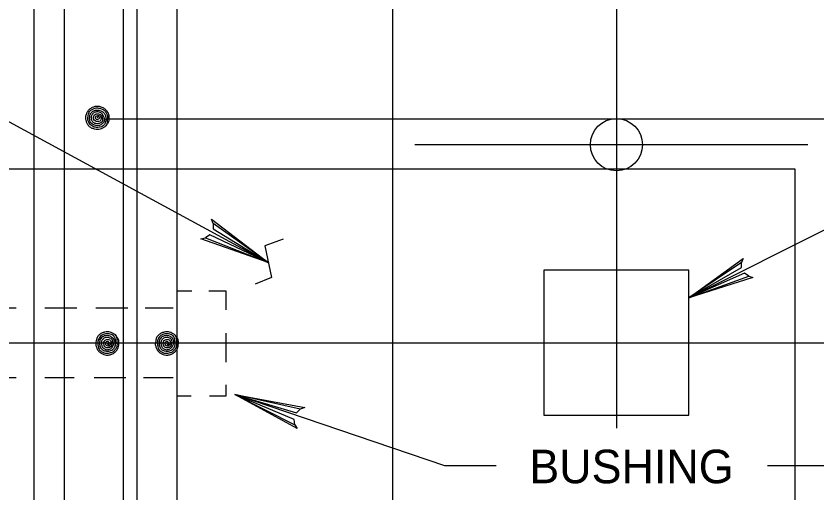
# Model space of a CAD drawing. Extents: x 638455 to 640199, y 298558 to 299152.
# Drawn here: x 638610.5 to 638690.8, y 298970 to 299017.7 of the extents above; entities that cross this region are included whole.
import ezdxf

# ---------------------------------------------------------------- set-up
doc = ezdxf.new("R2010")
doc.units = 0
for name, color, linetype in [('1', 7, 'Continuous'), ('2', 7, 'Continuous'), ('3', 7, 'Continuous')]:
    doc.layers.add(name, color=color, linetype=linetype)

msp = doc.modelspace()

# ---------------------------------------------------------------- linework, layer by layer
at = {"layer": '1'}
msp.add_line((638677.909, 298989.513), (638734.068, 299017.707), dxfattribs=at)
for points in [[(638630.234, 298996.977), (638630.224, 298996.432), (638635.736, 298993.066), (638630.234, 298996.977), (638630.071, 298997.399), (638635.736, 298993.066), (638629.909, 298995.835), (638629.475, 298995.524), (638635.736, 298993.066), (638629.004, 298995.413), (638629.475, 298995.524)], [(638637.232, 298995.376), (638635.411, 298994.726), (638636.062, 298991.537), (638634.436, 298990.886)], [(638638.428, 298976.809), (638638.353, 298977.349), (638632.389, 298979.827), (638638.428, 298976.809), (638638.654, 298976.418), (638632.389, 298979.827), (638638.573, 298977.988), (638638.954, 298978.362), (638632.389, 298979.827), (638639.403, 298978.544), (638638.954, 298978.362)]]:
    msp.add_lwpolyline(points, dxfattribs=at)
at = {"layer": '2'}
for p, q in [((638670.649, 299048.639), (638670.649, 298976.455)), ((638612.27, 298943.574), (638612.27, 299043.396)), ((638615.328, 298928.815), (638615.328, 299041.293)), ((638648.201, 299038.114), (638648.201, 298931.255)), ((638604.496, 299009.982), (638635.736, 298993.066)), ((638619.544, 299007.452), (638722.162, 299007.452)), ((638689.832, 299004.854), (638650.452, 299004.854)), ((638529.296, 299002.44), (638688.53, 299002.44)), ((638688.53, 299002.44), (638688.53, 298967.592)), ((638628.1, 298990.171), (638626.618, 298990.171)), ((638631.515, 298990.171), (638629.787, 298990.171)), ((638631.515, 298988.317), (638631.515, 298990.171)), ((638589.155, 298988.501), (638610.465, 298988.501)), ((638613.346, 298988.501), (638616.545, 298988.501)), ((638618.481, 298988.501), (638621.667, 298988.501)), ((638623.416, 298988.501), (638626.218, 298988.501)), ((638631.515, 298983.063), (638631.515, 298985.971)), ((638582.78, 298985.016), (638777.126, 298985.016)), ((638625.981, 298985.016), (638633.388, 298985.016)), ((638589.155, 298981.532), (638610.465, 298981.532)), ((638613.346, 298981.532), (638616.295, 298981.532)), ((638618.294, 298981.532), (638621.479, 298981.532)), ((638623.228, 298981.532), (638626.218, 298981.532)), ((638631.515, 298979.717), (638631.515, 298980.812)), ((638626.618, 298979.717), (638628.038, 298979.717)), ((638629.849, 298979.717), (638631.515, 298979.717)), ((638653.457, 298972.684), (638632.389, 298979.827)), ((638658.603, 298972.684), (638653.457, 298972.684)), ((638699.805, 298972.684), (638685.801, 298972.684))]:
    msp.add_line(p, q, dxfattribs=at)
for points in [[(638621.251, 299034.415), (638720.048, 299034.415), (638720.048, 298935.618), (638621.251, 298935.618), (638621.251, 299034.415)], [(638622.593, 299033.135), (638718.705, 299033.135), (638718.705, 298937.023), (638622.593, 298937.023), (638622.593, 299033.135)], [(638626.618, 298940.985), (638626.618, 299029.048)], [(638683.913, 298991.672), (638683.494, 298991.971), (638677.909, 298989.513), (638683.913, 298991.672), (638684.326, 298991.569), (638677.909, 298989.513), (638683.202, 298992.539), (638683.194, 298993.043), (638677.909, 298989.513), (638683.363, 298993.467), (638683.194, 298993.043)]]:
    msp.add_lwpolyline(points, dxfattribs=at)
msp.add_lwpolyline([(638663.389, 298977.756), (638677.909, 298977.756), (638677.909, 298992.276), (638663.389, 298992.276)], close=True, dxfattribs=at)
msp.add_circle((638670.649, 299004.854), 2.614, dxfattribs=at)
for points in [[(638618.63, 299007.545), (638618.688, 299007.661), (638618.775, 299007.647), (638618.795, 299007.464), (638618.633, 299007.368), (638618.438, 299007.464), (638618.447, 299007.647), (638618.554, 299007.76), (638618.775, 299007.777), (638618.929, 299007.661), (638619.004, 299007.472), (638618.891, 299007.225), (638618.65, 299007.17), (638618.383, 299007.252), (638618.24, 299007.42), (638618.258, 299007.705), (638618.392, 299007.887), (638618.633, 299007.954), (638618.848, 299007.911), (638619.024, 299007.804), (638619.103, 299007.618), (638619.147, 299007.376), (638619.091, 299007.153), (638618.882, 299007.01), (638618.563, 299006.947), (638618.214, 299007.089), (638618.04, 299007.33), (638618.04, 299007.661), (638618.151, 299007.943), (638618.392, 299008.129), (638618.775, 299008.152), (638619.048, 299008.001), (638619.213, 299007.736), (638619.312, 299007.464), (638619.266, 299007.136), (638619.048, 299006.903), (638618.731, 299006.77), (638618.226, 299006.848), (638617.91, 299007.127), (638617.843, 299007.51), (638617.91, 299007.887), (638618.13, 299008.184), (638618.424, 299008.303), (638618.882, 299008.294), (638619.245, 299008.085), (638619.42, 299007.777), (638619.463, 299007.452), (638619.431, 299007.17), (638619.321, 299006.868), (638619.024, 299006.653), (638618.545, 299006.587), (638618.116, 299006.706), (638617.799, 299007.002), (638617.668, 299007.348), (638617.7, 299007.792), (638617.843, 299008.204), (638618.084, 299008.379), (638618.508, 299008.532), (638618.949, 299008.468), (638619.257, 299008.326), (638619.495, 299008.053), (638619.62, 299007.769), (638619.62, 299007.464), (638619.605, 299007.136), (638619.53, 299006.828), (638619.373, 299006.653), (638619.132, 299006.502), (638618.891, 299006.413), (638618.65, 299006.377), (638618.348, 299006.421), (638618.04, 299006.52), (638617.776, 299006.715), (638617.593, 299006.964), (638617.506, 299007.278), (638617.459, 299007.571), (638617.526, 299007.911), (638617.648, 299008.184), (638617.866, 299008.434), (638618.13, 299008.602), (638618.392, 299008.701), (638618.705, 299008.709), (638619.071, 299008.619), (638619.373, 299008.434), (638619.562, 299008.236), (638619.716, 299007.986), (638619.771, 299007.722), (638619.78, 299007.42), (638619.716, 299007.089), (638619.62, 299006.938), (638619.42, 299006.715)], [(638619.629, 298984.952), (638619.687, 298984.836), (638619.774, 298984.85), (638619.794, 298985.033), (638619.632, 298985.129), (638619.437, 298985.033), (638619.446, 298984.85), (638619.553, 298984.737), (638619.774, 298984.719), (638619.928, 298984.836), (638620.004, 298985.024), (638619.89, 298985.274), (638619.649, 298985.326), (638619.382, 298985.245), (638619.24, 298985.076), (638619.257, 298984.792), (638619.391, 298984.609), (638619.632, 298984.542), (638619.847, 298984.586), (638620.024, 298984.693), (638620.102, 298984.879), (638620.146, 298985.12), (638620.091, 298985.344), (638619.882, 298985.486), (638619.562, 298985.55), (638619.214, 298985.408), (638619.039, 298985.166), (638619.039, 298984.836), (638619.15, 298984.554), (638619.391, 298984.368), (638619.774, 298984.345), (638620.047, 298984.496), (638620.213, 298984.76), (638620.311, 298985.033), (638620.265, 298985.361), (638620.047, 298985.593), (638619.731, 298985.727), (638619.225, 298985.648), (638618.909, 298985.37), (638618.842, 298984.986), (638618.909, 298984.609), (638619.13, 298984.313), (638619.423, 298984.193), (638619.882, 298984.202), (638620.245, 298984.411), (638620.419, 298984.719), (638620.462, 298985.045), (638620.43, 298985.326), (638620.32, 298985.628), (638620.024, 298985.843), (638619.545, 298985.91), (638619.115, 298985.791), (638618.798, 298985.494), (638618.668, 298985.149), (638618.7, 298984.708), (638618.842, 298984.292), (638619.083, 298984.118), (638619.507, 298983.967), (638619.948, 298984.028), (638620.256, 298984.171), (638620.495, 298984.443), (638620.619, 298984.728), (638620.619, 298985.033), (638620.605, 298985.361), (638620.529, 298985.669), (638620.372, 298985.843), (638620.132, 298985.994), (638619.89, 298986.084), (638619.649, 298986.119), (638619.347, 298986.075), (638619.039, 298985.977), (638618.775, 298985.782), (638618.592, 298985.532), (638618.505, 298985.219), (638618.459, 298984.925), (638618.526, 298984.586), (638618.647, 298984.313), (638618.865, 298984.063), (638619.13, 298983.894), (638619.391, 298983.796), (638619.704, 298983.787), (638620.07, 298983.877), (638620.372, 298984.063), (638620.561, 298984.26), (638620.715, 298984.51), (638620.77, 298984.774), (638620.779, 298985.076), (638620.715, 298985.408), (638620.619, 298985.558), (638620.419, 298985.782)], [(638625.594, 298984.952), (638625.652, 298984.836), (638625.739, 298984.85), (638625.759, 298985.033), (638625.597, 298985.129), (638625.402, 298985.033), (638625.411, 298984.85), (638625.518, 298984.737), (638625.739, 298984.719), (638625.893, 298984.836), (638625.969, 298985.024), (638625.855, 298985.274), (638625.614, 298985.326), (638625.347, 298985.245), (638625.205, 298985.076), (638625.222, 298984.792), (638625.356, 298984.609), (638625.597, 298984.542), (638625.812, 298984.586), (638625.989, 298984.693), (638626.067, 298984.879), (638626.111, 298985.12), (638626.056, 298985.344), (638625.847, 298985.486), (638625.527, 298985.55), (638625.179, 298985.408), (638625.004, 298985.166), (638625.004, 298984.836), (638625.115, 298984.554), (638625.356, 298984.368), (638625.739, 298984.345), (638626.012, 298984.496), (638626.178, 298984.76), (638626.276, 298985.033), (638626.23, 298985.361), (638626.012, 298985.593), (638625.696, 298985.727), (638625.19, 298985.648), (638624.874, 298985.37), (638624.807, 298984.986), (638624.874, 298984.609), (638625.095, 298984.313), (638625.388, 298984.193), (638625.847, 298984.202), (638626.21, 298984.411), (638626.384, 298984.719), (638626.427, 298985.045), (638626.395, 298985.326), (638626.285, 298985.628), (638625.989, 298985.843), (638625.51, 298985.91), (638625.08, 298985.791), (638624.763, 298985.494), (638624.633, 298985.149), (638624.665, 298984.708), (638624.807, 298984.292), (638625.048, 298984.118), (638625.472, 298983.967), (638625.913, 298984.028), (638626.221, 298984.171), (638626.46, 298984.443), (638626.584, 298984.728), (638626.584, 298985.033), (638626.57, 298985.361), (638626.494, 298985.669), (638626.337, 298985.843), (638626.097, 298985.994), (638625.855, 298986.084), (638625.614, 298986.119), (638625.312, 298986.075), (638625.004, 298985.977), (638624.74, 298985.782), (638624.557, 298985.532), (638624.47, 298985.219), (638624.424, 298984.925), (638624.491, 298984.586), (638624.612, 298984.313), (638624.83, 298984.063), (638625.095, 298983.894), (638625.356, 298983.796), (638625.669, 298983.787), (638626.035, 298983.877), (638626.337, 298984.063), (638626.526, 298984.26), (638626.68, 298984.51), (638626.735, 298984.774), (638626.744, 298985.076), (638626.68, 298985.408), (638626.584, 298985.558), (638626.384, 298985.782)]]:
    msp.add_spline(points, degree=3, dxfattribs=at)

# ---------------------------------------------------------------- texts
at = {"layer": '3'}
msp.add_text('BUSHING', height=3.36, dxfattribs=at).set_placement((638661.921, 298970.948))

doc.saveas('drawing.dxf')
